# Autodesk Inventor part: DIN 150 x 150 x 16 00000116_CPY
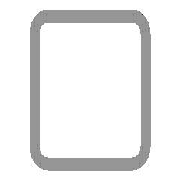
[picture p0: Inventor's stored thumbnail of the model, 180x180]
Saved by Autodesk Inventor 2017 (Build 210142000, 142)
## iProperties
Created: 2016-02
Part Number: DIN 150 x 150 x 16 00000116_CPY
Material: Steel, Mild
Description: Tube
Document SubType Name: Modeling
Standard: DIN
Designer: iusti
Standard Revision: 2006-07
Standards Organization: DIN
Language: en-US
Size Designation: 150 x 150 x 16
Categories: <MemberInstance><Categories><Category DisplayName="Structural Shapes" InternalName="089c4875-fa83-4c05-b084-43b9cc11f5ed" Mnemonic="GRDR"><CategoryParameter Dis
Stock Number: 150 x 150 x 16
Density: 7.85 g/cm^3
Appearance: Semi-Polished
IsCustomPart: 1
_CCFamilyMember: 70
_CCFamilyDisplayName: DIN EN 10210-2 (Square) - Tube — Sizes in parentheses have been withdrawn
_FrameMemberDoc: Frame Member File
_Version: 15.0.0
_GetPNFromCC: 1
Author: iusti
G_L: 2627.460 mm
G_W: 150.000 mm
G_H: 150.000 mm
+1C1875EB-09B4-4BC1-A3F9-F1E22132A380+CUTDETAIL1: Cut
+973DBC56-8C91-4BBB-AADC-B661641204C8+CUTDETAIL2: Cut
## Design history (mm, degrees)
node "Start plane"
node "End plane"
sketch "Sketch"
  geometry: L1 (-75, -51)-(-75, 51); L2 (-51, 75)-(51, 75); L3 (75, 51)-(75, -51); L4 (51, -75)-(-51, -75); L5 (-43, 59)-(43, 59); L6 (59, 43)-(59, -43); L7 (43, -59)-(-43, -59); L8 (-59, -43)-(-59, 43); L9 (0, 111.959)-(0, -111.959) reference; L10 (-111.959, 0)-(111.959, 0) reference; A1 r 24 centre (-51, -51) between (-75, -51) and (-51, -75); A2 r 24 centre (-51, 51) between (-51, 75) and (-75, 51); A3 r 24 centre (51, 51) between (75, 51) and (51, 75); A4 r 24 centre (51, -51) between (51, -75) and (75, -51); A5 r 16 centre (-43, -43) between (-59, -43) and (-43, -59); A6 r 16 centre (-43, 43) between (-43, 59) and (-59, 43); A7 r 16 centre (43, 43) between (59, 43) and (43, 59); A8 r 16 centre (43, -43) between (43, -59) and (59, -43)
  constraints: 16 end point, 16 point on circle, 16 tangent, 8 centre point, 6 equal radius, 4 parallel, 2 perpendicular, 2 other
  dimensions: "d7" = 24 radius of A1 (= G_IR); "d10" = 150 distance between parallel lines of L2 L4 (= G_H); "d11" = 150 distance between parallel lines of L1 L3 (= G_W); "d12" = 16 distance between parallel lines of L3 L6 (= G_T); "d15" = 75 distance between parallel lines of L2 L10 (= 0.5 x d10); "d16" = 75 distance between parallel lines of L9 L3 (= 0.5 x d11); "d19" = 16 radius of A5 (= G_T); "d20" = 16 distance between parallel lines of L4 L7 (= G_T)
extrude "Body" new body sketch "Sketch" stored distance "d3" = 2627.46034 (= G_L); taper "d4" = 0 deg
node "Driven Length"
  sketch "Sketch3"
    geometry: L1 (0, 0)-(10, 0) reference
    constraints: 2 end point, 1 horizontal
  workplane "Work Plane3"
  sketch "Sketch4"
    geometry: L1 (-2, 35.842)-(12, 35.842) reference; L2 (-2, 2663.303)-(12, 2663.303) reference
    dimensions: "d18" = 2627.46034 distance between parallel lines of L1 L2 (derived)
workplane "Work Plane4"
split "Split1"
workplane "Work Plane5"
split "Split2"
body "Solid1"
other parameters: "G_W" = 150 [user parameter; used in 1 equation term], "G_H" = 150 [user parameter; used in 1 equation term], "G_T" = 16 [user parameter; used in 3 equation terms], "G_IR" = 24 [user parameter; used in 1 equation term], "G_L" = 2627.46034 (= d18) [user parameter; used in 1 equation term], "G_OFFSET_START" = -35.84222 [user parameter; used in 1 equation term], "G_OFFSET_END" = 92.90179 [user parameter; used in 1 equation term], "d13" = 35.84222 (= -G_OFFSET_START), "d14" = 2663.30256 (= G_OFFSET_END + B_L), "B_L" = 2570.40077 [user parameter; used in 1 equation term], "d17" = 90 deg
